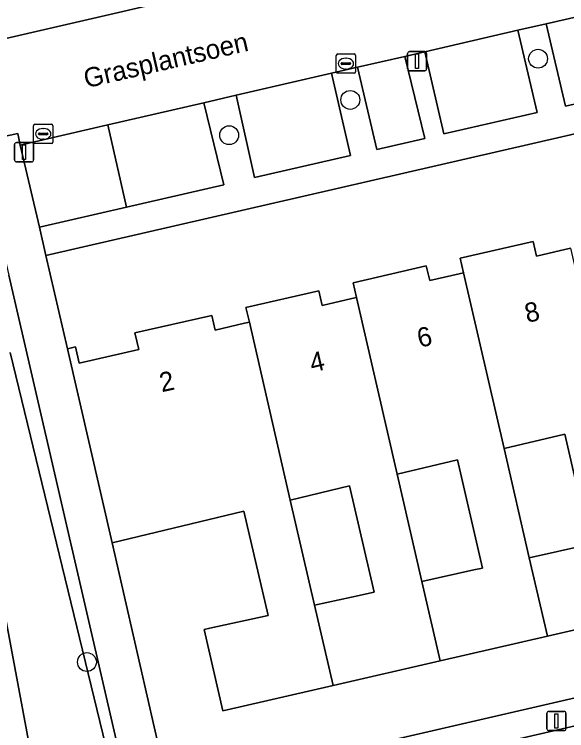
# Model space of a CAD drawing. Extents: x 156412 to 157779, y 382335 to 383768.
# Drawn here: x 156722.18 to 156750.81, y 382703.28 to 382740.43 of the extents above; entities that cross this region are included whole.
import ezdxf

# ---------------------------------------------------------------- set-up
doc = ezdxf.new("R2010")
doc.units = 0
for name, color, linetype in [('IMGEO_Berm_groen', 7, 'Continuous'), ('IMGEO_Boom', 7, 'Continuous'), ('IMGEO_Erf', 7, 'Continuous'), ('IMGEO_Greppel_droge_sloot', 7, 'Continuous'), ('IMGEO_Kolk', 7, 'Continuous'), ('IMGEO_Lichtmast', 7, 'Continuous'), ('IMGEO_Muur', 7, 'Continuous'), ('IMGEO_Openbare_ruimte_label', 7, 'Continuous'), ('IMGEO_Pand', 7, 'Continuous'), ('IMGEO_Pand_nummerreeks', 7, 'Continuous'), ('IMGEO_Parkeervlak_open', 7, 'Continuous'), ('IMGEO_Rijbaan_lokaal_gesloten', 7, 'Continuous'), ('IMGEO_Rijbaan_lokaal_open', 7, 'Continuous'), ('IMGEO_Voetpad_open', 7, 'Continuous')]:
    doc.layers.add(name, color=color, linetype=linetype)

msp = doc.modelspace()

# ---------------------------------------------------------------- linework, layer by layer
at = {"layer": 'IMGEO_Berm_groen'}
for points in [[(156722.872, 382699.769), (156728.301, 382699.143), (156721.886, 382726.902)], [(156721.962, 382722.89), (156727.065, 382701.905)], [(156723.259, 382700.896), (156719.259, 382722.217)]]:
    msp.add_lwpolyline(points, dxfattribs=at)
at = {"layer": 'IMGEO_Boom'}
for centre in [(156749.324, 382738.129), (156739.593, 382735.99), (156733.313, 382734.159), (156725.941, 382706.834)]:
    msp.add_circle(centre, 0.489, dxfattribs=at)
at = {"layer": 'IMGEO_Erf'}
msp.add_lwpolyline([(156794.348, 382744.171), (156723.806, 382727.923), (156724.941, 382723.085), (156725.34, 382723.18), (156725.537, 382722.33), (156728.626, 382723.043), (156728.425, 382723.913), (156732.411, 382724.808), (156732.586, 382724.049), (156734.113, 382724.403), (156734.359, 382724.46), (156734.184, 382725.218), (156737.967, 382726.094), (156738.142, 382725.335), (156739.669, 382725.689), (156739.912, 382725.745), (156739.739, 382726.496), (156743.531, 382727.379), (156743.706, 382726.62), (156745.233, 382726.974), (156745.464, 382727.028), (156745.291, 382727.777), (156749.077, 382728.65), (156749.252, 382727.891), (156750.779, 382728.245), (156751.019, 382728.3)], dxfattribs=at)
for points in [[(156790.128, 382713.958), (156800.769, 382716.402), (156800.687, 382716.754), (156799.998, 382719.724), (156794.242, 382718.399), (156788.688, 382717.12), (156783.133, 382715.842), (156777.58, 382714.563), (156772.025, 382713.284), (156766.472, 382712.006), (156760.917, 382710.727), (156755.363, 382709.449), (156749.81, 382708.17), (156744.255, 382706.892), (156738.701, 382705.613), (156732.984, 382704.297), (156732.018, 382708.516), (156732.308, 382708.586), (156735.332, 382709.254), (156734.066, 382714.657), (156727.251, 382713.017), (156729.431, 382703.479), (156730.2, 382700.114)], [(156747.566, 382717.906), (156748.871, 382712.245), (156751.948, 382712.924), (156752.025, 382712.941), (156750.707, 382718.662)], [(156742.025, 382716.572), (156743.305, 382711.015), (156745.995, 382711.609), (156746.449, 382711.709), (156745.155, 382717.326)], [(156736.483, 382715.239), (156737.74, 382709.786), (156739.651, 382710.208), (156740.822, 382710.467), (156739.553, 382715.977)]]:
    msp.add_lwpolyline(points, close=True, dxfattribs=at)
at = {"layer": 'IMGEO_Greppel_droge_sloot'}
for points in [[(156727.065, 382701.905), (156721.962, 382722.89)], [(156719.259, 382722.217), (156723.259, 382700.896)]]:
    msp.add_lwpolyline(points, dxfattribs=at)
at = {"layer": 'IMGEO_Kolk'}
for p, q in [((156738.864, 382737.447), (156738.864, 382738.299)), ((156738.939, 382738.373), (156739.791, 382738.373)), ((156739.352, 382738.153), (156739.377, 382738.153)), ((156739.865, 382738.299), (156739.865, 382737.447)), ((156739.123, 382737.867), (156739.123, 382737.879)), ((156739.561, 382737.83), (156739.163, 382737.83)), ((156739.166, 382737.916), (156739.564, 382737.916)), ((156739.607, 382737.879), (156739.607, 382737.867)), ((156739.791, 382737.373), (156738.939, 382737.373)), ((156739.375, 382737.593), (156739.35, 382737.593)), ((156723.173, 382733.801), (156723.173, 382734.653)), ((156723.248, 382734.727), (156724.1, 382734.727)), ((156723.661, 382734.507), (156723.686, 382734.507)), ((156724.174, 382734.653), (156724.174, 382733.801)), ((156723.432, 382734.221), (156723.432, 382734.233)), ((156723.87, 382734.184), (156723.472, 382734.184)), ((156723.475, 382734.27), (156723.873, 382734.27)), ((156723.916, 382734.233), (156723.916, 382734.221)), ((156724.1, 382733.727), (156723.248, 382733.727)), ((156723.684, 382733.947), (156723.659, 382733.947))]:
    msp.add_line(p, q, dxfattribs=at)
for points in [[(156738.864, 382737.447), (156738.864, 382738.299)], [(156738.939, 382738.373), (156739.791, 382738.373)], [(156739.865, 382738.299), (156739.865, 382737.447)], [(156739.791, 382737.373), (156738.939, 382737.373)], [(156723.173, 382733.801), (156723.173, 382734.653)], [(156723.248, 382734.727), (156724.1, 382734.727)], [(156724.174, 382734.653), (156724.174, 382733.801)], [(156724.1, 382733.727), (156723.248, 382733.727)]]:
    msp.add_lwpolyline(points, dxfattribs=at)
for centre, radius, start, end in [((156738.941, 382738.297), 0.0765, 91.552, 178.448), ((156738.941, 382738.297), 0.0765, 91.552, 178.448), ((156739.789, 382738.297), 0.0765, 1.552, 88.448), ((156739.789, 382738.297), 0.0765, 1.552, 88.448), ((156739.163, 382737.876), 0.0403, 85.8775, 175.7526), ((156739.16, 382737.866), 0.0366, 178.938, 274.7102), ((156739.564, 382737.873), 0.043, 264.8664, 352.4533), ((156739.568, 382737.878), 0.0386, 1.7309, 96.639), ((156738.941, 382737.449), 0.0765, 181.552, 268.448), ((156738.941, 382737.449), 0.0765, 181.552, 268.448), ((156739.789, 382737.449), 0.0765, 271.552, 358.448), ((156739.789, 382737.449), 0.0765, 271.552, 358.448), ((156723.25, 382734.651), 0.0765, 91.552, 178.448), ((156723.25, 382734.651), 0.0765, 91.552, 178.448), ((156724.098, 382734.651), 0.0765, 1.552, 88.448), ((156724.098, 382734.651), 0.0765, 1.552, 88.448), ((156723.472, 382734.23), 0.0403, 85.8775, 175.7526), ((156723.469, 382734.22), 0.0366, 178.938, 274.7102), ((156723.873, 382734.227), 0.043, 264.8664, 352.4533), ((156723.877, 382734.232), 0.0386, 1.7309, 96.639), ((156723.25, 382733.803), 0.0765, 181.552, 268.448), ((156723.25, 382733.803), 0.0765, 181.552, 268.448), ((156724.098, 382733.803), 0.0765, 271.552, 358.448), ((156724.098, 382733.803), 0.0765, 271.552, 358.448)]:
    msp.add_arc(centre, radius, start, end, dxfattribs=at)
for centre, major_axis, ratio, start_param, end_param in [((156739.351, 382737.873), (-0.387, 0.002), 0.722429, 4.712389, 7.853982), ((156739.376, 382737.873), (-0.39, 0.002), 0.717154, 1.570796, 4.712389), ((156723.66, 382734.227), (-0.387, 0.002), 0.722429, 4.712389, 7.853982), ((156723.685, 382734.227), (-0.39, 0.002), 0.717154, 1.570796, 4.712389)]:
    msp.add_ellipse(centre, major_axis=major_axis, ratio=ratio, start_param=start_param, end_param=end_param, dxfattribs=at)
at = {"layer": 'IMGEO_Lichtmast'}
for p, q in [((156742.659, 382738.5), (156743.449, 382738.5)), ((156743.449, 382738.5), (156742.659, 382738.5)), ((156742.559, 382737.6), (156742.559, 382738.4)), ((156742.559, 382738.4), (156742.559, 382737.6)), ((156743.549, 382738.4), (156743.549, 382737.6)), ((156743.549, 382737.6), (156743.549, 382738.4)), ((156743.449, 382737.5), (156742.659, 382737.5)), ((156742.659, 382737.5), (156743.449, 382737.5)), ((156722.186, 382732.879), (156722.186, 382733.679)), ((156722.186, 382733.679), (156722.186, 382732.879)), ((156722.286, 382733.779), (156723.076, 382733.779)), ((156723.076, 382733.779), (156722.286, 382733.779)), ((156723.176, 382733.679), (156723.176, 382732.879)), ((156723.176, 382732.879), (156723.176, 382733.679)), ((156723.076, 382732.779), (156722.286, 382732.779)), ((156722.286, 382732.779), (156723.076, 382732.779)), ((156749.78, 382703.377), (156749.78, 382704.177)), ((156749.78, 382704.177), (156749.78, 382703.377)), ((156749.88, 382704.277), (156750.67, 382704.277)), ((156750.67, 382704.277), (156749.88, 382704.277)), ((156750.77, 382704.177), (156750.77, 382703.377)), ((156750.77, 382703.377), (156750.77, 382704.177)), ((156750.67, 382703.277), (156749.88, 382703.277)), ((156749.88, 382703.277), (156750.67, 382703.277))]:
    msp.add_line(p, q, dxfattribs=at)
for points in [[(156742.979, 382738.375), (156743.129, 382738.375), (156743.129, 382737.625), (156742.979, 382737.625), (156742.979, 382738.375)], [(156722.606, 382733.654), (156722.756, 382733.654), (156722.756, 382732.904), (156722.606, 382732.904), (156722.606, 382733.654)], [(156750.2, 382704.152), (156750.35, 382704.152), (156750.35, 382703.402), (156750.2, 382703.402), (156750.2, 382704.152)]]:
    msp.add_lwpolyline(points, dxfattribs=at)
for centre, start, end in [((156742.659, 382738.4), 90, 180), ((156742.659, 382738.4), 90, 180), ((156743.449, 382738.4), 0, 90), ((156743.449, 382738.4), 360, 90), ((156742.659, 382737.6), 180, 270), ((156742.659, 382737.6), 180, 270), ((156743.449, 382737.6), 270, 0), ((156743.449, 382737.6), 270, 0), ((156722.286, 382733.679), 90, 180), ((156722.286, 382733.679), 90, 180), ((156723.076, 382733.679), 0, 90), ((156723.076, 382733.679), 360, 90), ((156722.286, 382732.879), 180, 270), ((156722.286, 382732.879), 180, 270), ((156723.076, 382732.879), 270, 0), ((156723.076, 382732.879), 270, 0), ((156749.88, 382704.177), 90, 180), ((156749.88, 382704.177), 90, 180), ((156750.67, 382704.177), 0, 90), ((156750.67, 382704.177), 360, 90), ((156749.88, 382703.377), 180, 270), ((156749.88, 382703.377), 180, 270), ((156750.67, 382703.377), 270, 0), ((156750.67, 382703.377), 270, 0)]:
    msp.add_arc(centre, 0.1, start, end, dxfattribs=at)
at = {"layer": 'IMGEO_Muur'}
msp.add_lwpolyline([(156727.251, 382713.017), (156729.431, 382703.479)], dxfattribs=at)
at = {"layer": 'IMGEO_Pand'}
for points in [[(156753.107, 382719.239), (156751.019, 382728.3), (156750.779, 382728.245), (156749.252, 382727.891), (156749.077, 382728.65), (156745.291, 382727.777), (156745.464, 382727.028), (156747.566, 382717.906), (156750.707, 382718.662), (156752.025, 382712.941), (156751.948, 382712.924), (156748.871, 382712.245), (156749.81, 382708.17), (156755.363, 382709.449), (156754.436, 382713.474)], [(156747.566, 382717.906), (156745.464, 382727.028), (156745.233, 382726.974), (156743.706, 382726.62), (156743.531, 382727.379), (156739.739, 382726.496), (156739.912, 382725.745), (156742.025, 382716.572), (156745.155, 382717.326), (156746.449, 382711.709), (156745.995, 382711.609), (156743.305, 382711.015), (156744.255, 382706.892), (156749.81, 382708.17), (156748.871, 382712.245)], [(156734.359, 382724.46), (156736.483, 382715.239), (156739.553, 382715.977), (156740.822, 382710.467), (156739.651, 382710.208), (156737.74, 382709.786), (156738.701, 382705.613), (156744.255, 382706.892), (156743.305, 382711.015), (156742.025, 382716.572), (156739.912, 382725.745), (156739.669, 382725.689), (156738.142, 382725.335), (156737.967, 382726.094), (156734.184, 382725.218)], [(156738.701, 382705.613), (156737.74, 382709.786), (156736.483, 382715.239), (156734.359, 382724.46), (156734.113, 382724.403), (156732.586, 382724.049), (156732.411, 382724.808), (156728.425, 382723.913), (156728.626, 382723.043), (156725.537, 382722.33), (156725.34, 382723.18), (156724.941, 382723.085), (156727.251, 382713.017), (156734.066, 382714.657), (156735.332, 382709.254), (156732.308, 382708.586), (156732.018, 382708.516), (156732.984, 382704.297)]]:
    msp.add_lwpolyline(points, close=True, dxfattribs=at)
at = {"layer": 'IMGEO_Parkeervlak_open'}
for points in [[(156756.708, 382741.545), (156749.752, 382739.941), (156750.745, 382735.675), (156757.767, 382737.294)], [(156748.284, 382739.602), (156743.453, 382738.488), (156744.446, 382734.223), (156749.281, 382735.337)], [(156742.426, 382738.251), (156739.965, 382737.684), (156740.967, 382733.421), (156743.454, 382733.994)], [(156738.618, 382737.373), (156733.678, 382736.233), (156734.633, 382731.961), (156739.598, 382733.105)], [(156732.006, 382735.848), (156727.023, 382734.698), (156727.989, 382730.429), (156733.037, 382731.593)]]:
    msp.add_lwpolyline(points, close=True, dxfattribs=at)
at = {"layer": 'IMGEO_Rijbaan_lokaal_gesloten'}
msp.add_lwpolyline([(156830.11, 382764.227), (156721.265, 382739.07), (156719.193, 382738.591), (156720.275, 382733.806), (156722.355, 382734.245), (156722.474, 382733.649), (156727.023, 382734.698), (156732.006, 382735.848), (156733.678, 382736.233), (156738.618, 382737.373), (156739.965, 382737.684), (156742.426, 382738.251), (156743.453, 382738.488), (156748.284, 382739.602), (156749.752, 382739.941), (156756.708, 382741.545)], dxfattribs=at)
at = {"layer": 'IMGEO_Rijbaan_lokaal_open'}
msp.add_lwpolyline([(156954.997, 382755.422), (156950.885, 382751.332), (156949.815, 382749.383), (156929.495, 382744.678), (156907.413, 382739.578), (156879.275, 382733.088), (156868.803, 382730.665), (156830.401, 382721.812), (156805.031, 382715.955), (156791.204, 382712.755), (156730.522, 382698.738), (156728.301, 382699.143), (156722.872, 382699.769)], dxfattribs=at)
msp.add_lwpolyline([(156727.023, 382734.698), (156722.474, 382733.649), (156723.477, 382729.389), (156727.989, 382730.429)], close=True, dxfattribs=at)
at = {"layer": 'IMGEO_Voetpad_open'}
for points in [[(156830.11, 382764.227), (156940.449, 382789.73), (156940.042, 382791.626), (156869.58, 382775.359), (156866.975, 382774.768), (156865.597, 382774.441), (156795.182, 382758.201), (156793.73, 382757.867), (156791.208, 382757.283), (156759.674, 382750), (156720.792, 382741.02), (156721.265, 382739.07)], [(156724.941, 382723.085), (156723.806, 382727.923), (156723.477, 382729.389), (156722.474, 382733.649), (156722.355, 382734.245), (156720.275, 382733.806), (156721.028, 382730.527), (156721.886, 382726.902), (156728.301, 382699.143), (156730.522, 382698.738), (156730.2, 382700.114), (156729.431, 382703.479), (156727.251, 382713.017)]]:
    msp.add_lwpolyline(points, close=True, dxfattribs=at)
for points in [[(156756.708, 382741.545), (156757.767, 382737.294), (156750.745, 382735.675), (156749.752, 382739.941), (156748.284, 382739.602), (156749.281, 382735.337), (156744.446, 382734.223), (156743.453, 382738.488), (156742.426, 382738.251), (156743.454, 382733.994), (156740.967, 382733.421), (156739.965, 382737.684), (156738.618, 382737.373), (156739.598, 382733.105), (156734.633, 382731.961), (156733.678, 382736.233), (156732.006, 382735.848), (156733.037, 382731.593), (156727.989, 382730.429), (156723.477, 382729.389), (156723.806, 382727.923), (156794.348, 382744.171)], [(156811.426, 382718.859), (156808.902, 382718.276), (156804.689, 382717.303), (156802.123, 382716.713), (156800.769, 382716.402), (156790.128, 382713.958), (156730.2, 382700.114), (156730.522, 382698.738), (156791.204, 382712.755), (156805.031, 382715.955), (156830.401, 382721.812)]]:
    msp.add_lwpolyline(points, dxfattribs=at)

# ---------------------------------------------------------------- texts
at = {"layer": 'IMGEO_Openbare_ruimte_label'}
msp.add_text('Grasplantsoen', height=1, rotation=13.0075, dxfattribs=at).set_placement((156725.902, 382736.595))
at = {"layer": 'IMGEO_Pand_nummerreeks'}
for s, rotation, p in [('8', 13.0119, (156748.759, 382724.421)), ('6', 13.0119, (156743.184, 382723.133)), ('4', 13.0119, (156737.614, 382721.846)), ('2', 12.1352, (156729.817, 382720.826))]:
    msp.add_text(s, height=1, rotation=rotation, dxfattribs=at).set_placement(p)

doc.saveas('drawing.dxf')
